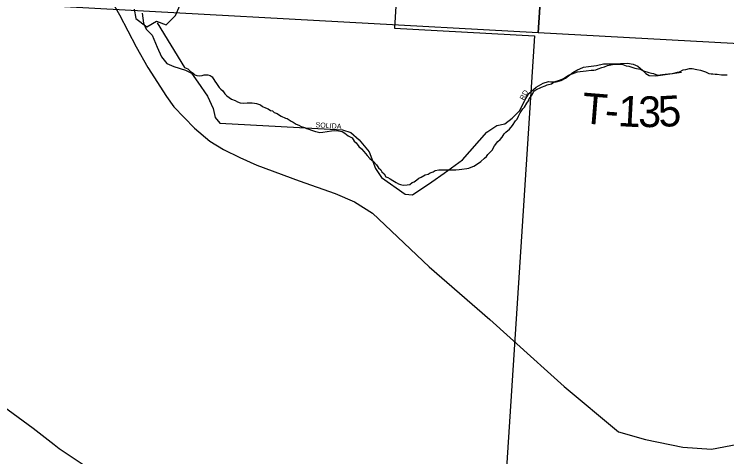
# Model space of a CAD drawing. Extents: x 1949938.81 to 1949945.61, y 152207.65 to 152214.09.
# Drawn here: x 1949941.387 to 1949942.704, y 152208.341 to 152209.158 of the extents above; entities that cross this region are included whole.
import ezdxf

# ---------------------------------------------------------------- set-up
doc = ezdxf.new("R2010")
doc.units = 0
for name, color, linetype in [('GM_X_City_Street', 7, 'Continuous'), ('GM_X_City_Street_Text', 7, 'Continuous'), ('GM_X_Corporation', 7, 'Continuous'), ('GM_X_Minor_River', 7, 'Continuous'), ('GM_X_Section', 7, 'Continuous'), ('GM_X_Township_Road', 7, 'Continuous'), ('GM_X_Township_Road_Text', 7, 'Continuous'), ('GM_X_US_Location', 7, 'Continuous'), ('GM_X_US_Route', 7, 'Continuous')]:
    doc.layers.add(name, color=color, linetype=linetype)

msp = doc.modelspace()

# ---------------------------------------------------------------- linework, layer by layer
at = {"layer": 'GM_X_City_Street'}
for points in [[(1949941.6235, 152209.1607), (1949941.6257, 152209.142), (1949941.6307, 152209.1306), (1949941.6422, 152209.1198), (1949941.6515, 152209.0976), (1949941.6594, 152209.0797), (1949941.6694, 152209.0675), (1949941.6823, 152209.0617), (1949941.7038, 152209.0553), (1949941.7146, 152209.0495), (1949941.7261, 152209.033), (1949941.744, 152209.0072), (1949941.7547, 152208.9843), (1949941.7584, 152208.9677), (1949941.7671, 152208.9573), (1949941.9935, 152208.9449), (1949942.0092, 152208.9399), (1949942.0243, 152208.9262), (1949942.0429, 152208.904), (1949942.0544, 152208.8732), (1949942.0659, 152208.8567), (1949942.1096, 152208.8258), (1949942.1232, 152208.8246), (1949942.1586, 152208.8488), (1949942.1817, 152208.8647), (1949942.2154, 152208.8893), (1949942.2605, 152208.9404), (1949942.2789, 152208.9527), (1949942.2937, 152208.9558), (1949942.3075, 152208.9665), (1949942.3213, 152208.9809), (1949942.3308, 152208.9995), (1949942.3378, 152209.0123), (1949942.3515, 152209.0239), (1949942.3648, 152209.0314), (1949942.3747, 152209.0339), (1949942.379, 152209.0337)], [(1949940.5981, 152209.1219), (1949940.6365, 152209.0736), (1949940.6848, 152209.0213), (1949940.7314, 152208.9693), (1949940.7666, 152208.9292), (1949940.8137, 152208.8783), (1949940.8731, 152208.8153), (1949940.9292, 152208.7573), (1949940.9589, 152208.7314), (1949941.0055, 152208.6895), (1949941.0412, 152208.6613), (1949941.1059, 152208.6151), (1949941.1469, 152208.5864), (1949941.2377, 152208.5233), (1949941.3066, 152208.4754), (1949941.3664, 152208.4347), (1949941.422, 152208.3939), (1949941.4607, 152208.3637)], [(1949941.4607, 152208.3637), (1949941.4704, 152208.3561), (1949941.5442, 152208.3067), (1949941.5804, 152208.2827), (1949941.6108, 152208.2664), (1949941.689, 152208.2426), (1949941.7287, 152208.2292), (1949941.7858, 152208.2124), (1949941.8203, 152208.2034), (1949941.8437, 152208.1989)]]:
    msp.add_lwpolyline(points, dxfattribs=at)
at = {"layer": 'GM_X_Corporation'}
msp.add_lwpolyline([(1949942.1062, 152209.4059), (1949942.0896, 152209.1325), (1949942.3484, 152209.1187), (1949942.2928, 152208.2633), (1949942.1618, 152208.279), (1949942.0982, 152208.0722), (1949942.0477, 152208.0858), (1949941.8214, 152208.1567), (1949941.682, 152208.19), (1949941.6393, 152208.2075), (1949941.5072, 152208.2663), (1949941.4156, 152208.2992), (1949941.1468, 152208.4145), (1949940.9962, 152208.5094), (1949940.8932, 152208.5894), (1949940.8285, 152208.6338), (1949940.6601, 152208.7875), (1949940.5757, 152208.8589), (1949940.4882, 152208.9716), (1949940.3947, 152209.1158), (1949940.3383, 152209.2145)], dxfattribs=at)
at = {"layer": 'GM_X_Minor_River'}
for points in [[(1949941.6089, 152209.1678), (1949941.6118, 152209.1503), (1949941.6322, 152209.135), (1949941.6497, 152209.1456), (1949941.6678, 152209.1387), (1949941.6853, 152209.1561), (1949941.693, 152209.1743)], [(1949941.6514, 152209.1428), (1949941.7015, 152209.0601), (1949941.7079, 152209.0577), (1949941.712, 152209.0534), (1949941.7176, 152209.0496), (1949941.7209, 152209.0468), (1949941.7247, 152209.0453), (1949941.7292, 152209.0444), (1949941.7342, 152209.0451), (1949941.738, 152209.0462), (1949941.7448, 152209.0464), (1949941.7493, 152209.0452)], [(1949942.2561, 152208.8923), (1949942.26, 152208.8957), (1949942.2623, 152208.8995), (1949942.2704, 152208.9073), (1949942.2747, 152208.9152), (1949942.2805, 152208.9235), (1949942.2848, 152208.9272), (1949942.2886, 152208.9313), (1949942.2922, 152208.9373), (1949942.2956, 152208.9407), (1949942.3022, 152208.9459), (1949942.3076, 152208.9526), (1949942.3134, 152208.9613), (1949942.3165, 152208.9646), (1949942.3192, 152208.9699), (1949942.322, 152208.976), (1949942.3267, 152208.9835), (1949942.3298, 152208.9868), (1949942.3341, 152208.9944), (1949942.3372, 152208.9985), (1949942.3387, 152209.0023), (1949942.3442, 152209.0094), (1949942.3473, 152209.0162), (1949942.3512, 152209.0188), (1949942.3615, 152209.0235), (1949942.3683, 152209.0261), (1949942.3722, 152209.0279), (1949942.3798, 152209.0301), (1949942.3851, 152209.0338), (1949942.3947, 152209.0366), (1949942.3996, 152209.0385), (1949942.4031, 152209.0403), (1949942.4111, 152209.0459), (1949942.4184, 152209.0484), (1949942.4283, 152209.052), (1949942.4328, 152209.0527), (1949942.4442, 152209.054), (1949942.4533, 152209.055), (1949942.4579, 152209.0553), (1949942.4617, 152209.056), (1949942.4662, 152209.0575), (1949942.4731, 152209.06), (1949942.4781, 152209.0614), (1949942.4834, 152209.0636), (1949942.4929, 152209.0654), (1949942.4982, 152209.066), (1949942.5028, 152209.066), (1949942.5115, 152209.0654), (1949942.5179, 152209.0634), (1949942.5231, 152209.0622), (1949942.5341, 152209.0586), (1949942.5435, 152209.0569), (1949942.548, 152209.0546), (1949942.5601, 152209.0506), (1949942.5646, 152209.0497), (1949942.5684, 152209.0489), (1949942.5725, 152209.0469), (1949942.5766, 152209.0457), (1949942.585, 152209.0471), (1949942.5899, 152209.0478), (1949942.5964, 152209.0484), (1949942.6036, 152209.0491), (1949942.6127, 152209.0512), (1949942.6165, 152209.0523), (1949942.6234, 152209.0556), (1949942.6284, 152209.0566), (1949942.6352, 152209.058), (1949942.6397, 152209.0579), (1949942.6484, 152209.0563), (1949942.6552, 152209.055), (1949942.6646, 152209.0522), (1949942.6707, 152209.0491), (1949942.6748, 152209.0486), (1949942.6782, 152209.0482), (1949942.6824, 152209.0477), (1949942.6858, 152209.0477), (1949942.6941, 152209.0467), (1949942.7043, 152209.0462)], [(1949941.7493, 152209.0452), (1949941.7531, 152209.0425), (1949941.7578, 152209.0348), (1949941.7608, 152209.0306), (1949941.766, 152209.0233), (1949941.7689, 152209.0198), (1949941.7727, 152209.0167), (1949941.7764, 152209.0113), (1949941.7797, 152209.0075), (1949941.7887, 152209.0013), (1949941.7951, 152208.9989), (1949941.7996, 152208.9965), (1949941.8045, 152208.9949), (1949941.8102, 152208.9944), (1949941.8174, 152208.9947), (1949941.8212, 152208.9946), (1949941.8268, 152208.9945), (1949941.831, 152208.9941), (1949941.8351, 152208.9933), (1949941.8419, 152208.9912), (1949941.846, 152208.9881), (1949941.8517, 152208.9858), (1949941.8562, 152208.9834), (1949941.8607, 152208.9807), (1949941.8641, 152208.9799), (1949941.8674, 152208.9771), (1949941.8731, 152208.9751), (1949941.8772, 152208.9717), (1949941.8806, 152208.9701), (1949941.8881, 152208.9665), (1949941.8915, 152208.9657), (1949941.899, 152208.9607), (1949941.9024, 152208.9591), (1949941.908, 152208.9552), (1949941.9132, 152208.9536), (1949941.9174, 152208.9509), (1949941.9234, 152208.9492), (1949941.9275, 152208.9476), (1949941.9313, 152208.9464), (1949941.9366, 152208.9441), (1949941.9437, 152208.9421), (1949941.9471, 152208.9412), (1949941.952, 152208.94), (1949941.9573, 152208.9403), (1949941.9653, 152208.9421), (1949941.9733, 152208.9431), (1949941.979, 152208.9434), (1949941.9866, 152208.9432), (1949941.993, 152208.9416), (1949941.9982, 152208.9389), (1949942.0042, 152208.9338), (1949942.0113, 152208.9303), (1949942.0154, 152208.9238), (1949942.0187, 152208.9207), (1949942.0239, 152208.9141), (1949942.0291, 152208.9095), (1949942.0329, 152208.9048), (1949942.0395, 152208.8975), (1949942.0444, 152208.8917), (1949942.0511, 152208.8863), (1949942.0567, 152208.8801), (1949942.0604, 152208.8748), (1949942.0645, 152208.8709), (1949942.0667, 152208.8674), (1949942.0708, 152208.8636), (1949942.0741, 152208.8582), (1949942.0775, 152208.8566), (1949942.082, 152208.8546), (1949942.0868, 152208.8511), (1949942.0928, 152208.8476), (1949942.097, 152208.8453), (1949942.1007, 152208.8441), (1949942.106, 152208.8428), (1949942.1132, 152208.8431), (1949942.1181, 152208.8438), (1949942.1224, 152208.8475), (1949942.1262, 152208.8486), (1949942.1312, 152208.8523), (1949942.135, 152208.8556), (1949942.1388, 152208.8575), (1949942.1465, 152208.8615), (1949942.1522, 152208.8633), (1949942.156, 152208.8655), (1949942.161, 152208.8674), (1949942.1652, 152208.8696), (1949942.172, 152208.871), (1949942.177, 152208.8713), (1949942.1845, 152208.8708), (1949942.1906, 152208.8707), (1949942.1951, 152208.871), (1949942.1997, 152208.8713), (1949942.2031, 152208.8712), (1949942.2092, 152208.8715), (1949942.2145, 152208.8722), (1949942.2232, 152208.8732), (1949942.2274, 152208.8738), (1949942.2312, 152208.8757), (1949942.2362, 152208.8775), (1949942.2396, 152208.8797), (1949942.2492, 152208.8864), (1949942.2561, 152208.8923)]]:
    msp.add_lwpolyline(points, dxfattribs=at)
at = {"layer": 'GM_X_Section'}
for points in [[(1949941.3344, 152210.2133), (1949942.4221, 152210.1447), (1949942.3551, 152209.1241), (1949941.2772, 152209.1831)], [(1949942.4221, 152210.1447), (1949943.5439, 152210.0754), (1949943.4815, 152209.0627), (1949942.3551, 152209.1241)]]:
    msp.add_lwpolyline(points, close=True, dxfattribs=at)
at = {"layer": 'GM_X_Township_Road'}
msp.add_lwpolyline([(1949942.379, 152209.0337), (1949942.3886, 152209.0333), (1949942.398, 152209.0358), (1949942.4057, 152209.0405), (1949942.4191, 152209.0507), (1949942.427, 152209.0554), (1949942.4388, 152209.0607), (1949942.4486, 152209.0618), (1949942.4628, 152209.064), (1949942.4761, 152209.0669), (1949942.4919, 152209.0671), (1949942.5074, 152209.0674), (1949942.5203, 152209.0678), (1949942.5307, 152209.0661), (1949942.5396, 152209.0627), (1949942.548, 152209.0554), (1949942.5545, 152209.0489), (1949942.5607, 152209.0452), (1949942.5729, 152209.0449), (1949942.6204, 152209.0517)], dxfattribs=at)
at = {"layer": 'GM_X_US_Route'}
for points in [[(1949941.5294, 152209.2477), (1949941.5383, 152209.2335), (1949941.5818, 152209.1576), (1949941.6123, 152209.0983), (1949941.6342, 152209.0601), (1949941.6685, 152209.0062), (1949941.6823, 152208.9876), (1949941.7205, 152208.9478), (1949941.7486, 152208.9239), (1949941.7741, 152208.9085), (1949941.8038, 152208.8936), (1949941.8357, 152208.8798), (1949941.9137, 152208.8506), (1949941.9801, 152208.8272), (1949942.0156, 152208.8118), (1949942.0491, 152208.7911), (1949942.1538, 152208.692), (1949942.266, 152208.5946), (1949942.3472, 152208.5215)], [(1949942.3472, 152208.5215), (1949942.3663, 152208.5043), (1949942.4035, 152208.4709), (1949942.504, 152208.3868), (1949942.5534, 152208.373), (1949942.6225, 152208.3587), (1949942.6759, 152208.3548), (1949942.7371, 152208.3665), (1949942.7677, 152208.3764)]]:
    msp.add_lwpolyline(points, dxfattribs=at)

# ---------------------------------------------------------------- texts
at = {"layer": 'GM_X_City_Street_Text'}
for s, rotation, p in [('RD', 62.114, (1949942.3287, 152208.9987)), ('SOLIDA', 356.1861, (1949941.9437, 152208.9497))]:
    msp.add_text(s, height=0.00947, rotation=rotation, dxfattribs=at).set_placement(p)
at = {"layer": 'GM_X_Township_Road_Text'}
for s, rotation, p in [('T', 355.3396, (1949942.4345, 152208.9572)), ('1', 356.8641, (1949942.5017, 152208.9519)), ('3', 0.0586, (1949942.5402, 152208.9499)), ('5', 3.3701, (1949942.5787, 152208.95)), ('-', 355.6943, (1949942.4772, 152208.9537))]:
    msp.add_text(s, height=0.0568, rotation=rotation, dxfattribs=at).set_placement(p)
at = {"layer": 'GM_X_US_Location'}
for s in ['0', '/']:
    msp.add_text(s, height=0.000189, dxfattribs=at).set_placement((1949941.8794, 152208.8241))
msp.add_text('52', height=0.000189, rotation=0, dxfattribs=at).set_placement((1949941.8403, 152208.7849))

doc.saveas('drawing.dxf')
